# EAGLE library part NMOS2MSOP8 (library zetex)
Dual MOS FET
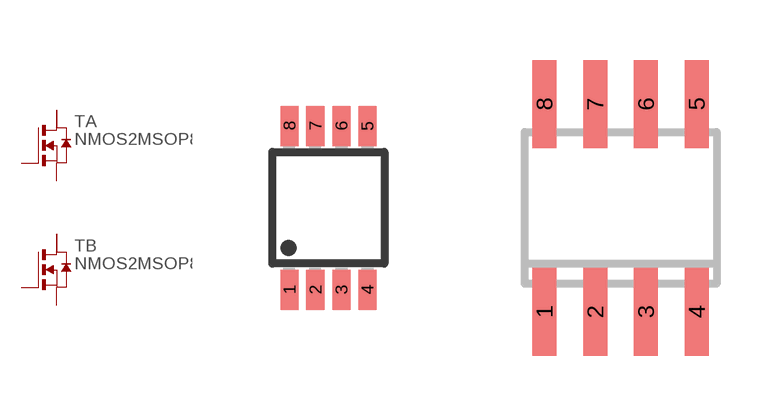
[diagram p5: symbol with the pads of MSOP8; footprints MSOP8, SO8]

Designator prefix T; gates A=N_MOS2D B=N_MOS2D

## NMOS2MSOP8 (OC_FARNELL: unknown; OC_NEWARK: unknown)  [MSOP8]
1  B:D  pas
2  B:D2  pas
3  A:D  pas
4  A:D2  pas
5  A:S  pas
6  A:G  pas
7  B:S  pas
8  B:G  pas

## NMOS2MSOP8SO8 (OC_FARNELL: unknown; OC_NEWARK: unknown)  [SO8]
Pads as for MSOP8

## Footprint MSOP8 (pad centres in mm)
Micro Small Outline Package
smd 0.45 x 1: 1 -0.975,-2.05; 2 -0.325,-2.05; 3 0.325,-2.05; 4 0.975,-2.05; 5 0.975,2.05; 6 0.325,2.05; 7 -0.325,2.05; 8 -0.975,2.05

## Footprint SO8 (pad centres in mm)
SMALL OUTLINE INTEGRATED CIRCUIT
smd 0.6 x 2.2: 1 -1.905,-2.6; 2 -0.635,-2.6; 3 0.635,-2.6; 4 1.905,-2.6; 5 1.905,2.6; 6 0.635,2.6; 7 -0.635,2.6; 8 -1.905,2.6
